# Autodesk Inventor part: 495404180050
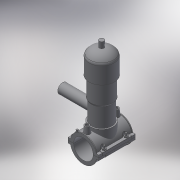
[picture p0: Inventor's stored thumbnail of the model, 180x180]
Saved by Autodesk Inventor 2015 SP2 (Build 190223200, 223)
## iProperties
Created: 2017-07
Part Number: 495404180050
Material: Generic
Description: PLASSON TAPPING VALVE 180-50
Document SubType Name: Modeling
Designer: KIM
Density: 1 g/cm^3
Appearance: Default
Author: KIM
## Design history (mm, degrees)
derived "495404-4954S4.ipt"
feature "Solid1::495404-4954S4.ipt"
feature "Solid2::495404-4954S4.ipt"
tag "TaggingFeature1"
body "Solid1"
body "Solid2"
other parameters: "d3" = 45, "d4" = 118, "d5" = 0, "d6" = 0.1, "d8" = 0, "d19" = 6, "d20" = 6, "d21" = 70.8, "d23" = 0, "d24" = 35.4, "d26" = 0, "d27" = 3, "d28" = 3, "d29" = 3, "d31" = 6, "d32" = 0, "d33" = 0, "d34" = 0.6, "d40" = 109.512, "d47" = 156.3, "d70" = 15, "d72" = 0, "d73" = 6, "d75" = 5, "d76" = 0, "d77" = 9, "d79" = 15, "d80" = 47.2, "d82" = 5 deg, "d84" = 4, "d85" = 14, "d86" = 0, "d87" = 3, "d88" = 0, "d89" = 1, "d90" = 1, "d91" = 94.4, "d92" = 0, "d93" = 0.5, "d94" = 94.73684, "d96" = 216.918, "d97" = 2.36, "d98" = 0, "d120" = 140 deg, "d121" = 24.228, "d122" = 20 deg, "d123" = 421.2, "d124" = 126.36, "d126" = 0, "d143" = 185.4, "d145" = 23.53846, "d149" = 2.7, "d150" = 25.89231, "d153" = 118, "d154" = 0, "d156" = 105.3, "d157" = 160 deg, "d159" = 6.12, "d161" = 2.7, "d162" = 70.8, "d163" = 0, "d167" = 18, "d168" = 102.73171, "d170" = 3, "d172" = 0, "d173" = 1, "d176" = 20 deg, "d177" = 12.6, "d178" = 30.6, "d180" = 0, "d183" = 12.24, "d184" = 10.08, "d185" = 38.35, "d186" = 38.35, "d187" = 105.3, "d188" = 9.18, "d189" = 12.6, "d190" = 0, "d191" = 157.95, "d193" = 6.8, "d194" = 2.95, "d195" = 90 deg, "d197" = 0, "d199" = 0, "d205" = 14.64, "d206" = 81.33333, "d207" = 244, "d208" = 224.48, "d209" = 207.4, "d210" = 200.08, "d211" = 146.4, "d212" = 85.4, "d213" = 65.88, "d214" = 73.2, "d216" = 19.52, "d217" = 70.76, "d218" = 80.52, "d222" = 0, "d223" = 210.6, "d224" = 152, "d225" = 51, "d229" = 152, "d230" = 0, "H_" = 152, "L_" = 118, "d_t" = 6, "H_1" = 51, "H_2" = 244, "d148" = 2.7, "d160" = 2.7, "d169" = 3, "d192" = 6.8
